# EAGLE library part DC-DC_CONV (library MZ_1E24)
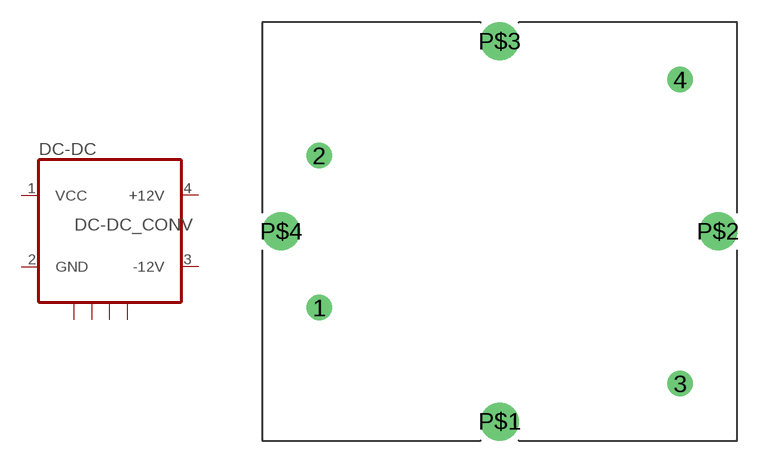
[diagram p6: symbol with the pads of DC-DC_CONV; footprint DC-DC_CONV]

Designator prefix DC-DC

## DC-DC_CONV  [DC-DC_CONV]
1  VCC  pwr
2  GND  pwr
3  -12V  pwr
4  +12V  pwr
P$1  GND  pwr
P$2  GND  pwr
P$3  GND  pwr
P$4  GND  pwr

## Footprint DC-DC_CONV (pad centres in mm)
drill 1.016 pad 1.676 round: 1 -12.065,-5.08; 2 -12.065,5.08; 3 12.065,-10.16; 4 12.065,10.16
drill 1 pad 2.54 round: P$1 0,-12.7; P$2 14.605,0; P$3 0,12.7; P$4 -14.605,0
